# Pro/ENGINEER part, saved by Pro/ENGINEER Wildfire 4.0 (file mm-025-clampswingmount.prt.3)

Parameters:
  METRIC = "NO"

Other parameters: PITCH, DRILL_DIAMETER, THREAD_DIAMETER, THREADS_PER_INCH, CBORE_DIAMETER, CBORE_DEPTH, DRILL_POINT_ANGLE, DRILL_DEPTH, THREAD_DEPTH, THREAD_LENGTH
